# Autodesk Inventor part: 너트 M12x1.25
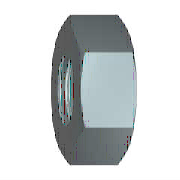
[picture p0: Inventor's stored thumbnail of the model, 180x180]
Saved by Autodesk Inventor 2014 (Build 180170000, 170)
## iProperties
IsCustomPart: 1
Created: 2012-02
Part Number: 너트 M12x1.25
Material: 강철, 연강
Description: 6각 너트
Document SubType Name: Modeling
Standard: KS B 1012
Designer: mduedu
Standards Organization: KS
Language: ko-KR
Size Designation: M12x1.25
Categories: <MemberInstance><Categories><Category DisplayName="조임쇠" InternalName="e4da775c-781d-43d5-af7c-5136215cf5a6" Mnemonic="FSTN"><Category DisplayName="너트" InternalN
Density: 1 g/cm^3
Appearance: 강철
Author: mduedu
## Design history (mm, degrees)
sketch "스케치1"
  geometry: L1 (-10.97, 0)-(-5.485, 9.5); L2 (-5.485, 9.5)-(5.485, 9.5); L3 (5.485, 9.5)-(10.97, 0); L4 (10.97, 0)-(5.485, -9.5); L5 (5.485, -9.5)-(-5.485, -9.5); L6 (-5.485, -9.5)-(-10.97, 0); 2 further points
  constraints: 12 end point, 1 coincident, 1 horizontal, 11 other
  dimensions: "d0" = 21.93931 distance of L3.end L1.start (= 1.1547 x SW)
extrude "본체" new body sketch "스케치1" distance "d1" = 10 (= KOH); taper "d2" = 0 deg
sketch "스케치2"
  geometry: L1 (0, 5.485)-(0, 10.97) reference; L2 (0, 10.97)-(10, 10.97) reference; L3 (10, 5.485)-(10, 10.97) reference; L4 (-2, 0)-(12, 0) reference; L5 (0.849, 10.97)-(0, 9.5); L6 (9.151, 10.97)-(10, 9.5)
  constraints: 4 end point, 4 point on line
  dimensions: "d3" = 30 deg angle of L1 L5 (= ANG1); "d4" = 30 deg angle of L3 L6 (= ANG2); "d5" = 19 diameter of L5.end L4 (= SW0); "d6" = 19 diameter of L6.end L4 (= SW01)
revolve "모따기1" sketch "스케치2" stored, may be unused: angle "d7" = 90 deg
sketch "스케치3"
  geometry: A1 r 9.5 centre (0, 0) between (-4.75, -8.227) and (4.75, -8.227) reference; 1 further point
  constraints: 1 coincident
hole "스레드" sketch "스케치3" at (0, 0) diameter "d25" = 10.647; stored, may be unused: countersink angle "d29" = 82 deg, drill point angle "d31" = 118 deg; dims "d26" = 6, "d27" = 4, "d28" = 2, "d30" = 8
workaxis "Work Axis1"
workplane "Work Plane1"
body "Solid1"
chamfer "모따기2" distance "d8" = 0.67658 (= -0.5 x GD1 + 0.5 x NND); stored, may be unused: angle "d9" = 30 deg, second distance "d40" = 0.67658 (= -0.5 x GD1 + 0.5 x NND)
chamfer "모따기3" distance "d10" = 0.67658 (= -0.5 x GD1 + 0.5 x NND); stored, may be unused: angle "d11" = 30 deg, second distance "d41" = 0.67658 (= -0.5 x GD1 + 0.5 x NND)
other parameters: "ANG1" = 30 deg [user parameter; used in 1 equation term], "ANG2" = 30 deg [user parameter; used in 1 equation term], "NND" = 12 [user parameter; used in 4 equation terms], "KOH" = 10 [user parameter; used in 1 equation term], "SW" = 19 [user parameter; used in 4 equation terms], "SW0" = 19 (= SW) [user parameter; used in 1 equation term], "SW01" = 19 (= SW) [user parameter; used in 1 equation term], "GD1" = 10.64684 (computed from THREADDIA, PTC, TOA) [user parameter; used in 4 equation terms], "d13" = 0, "d14" = 0, "d39" = 0, "d42" = 0, "GUL" = 0.67658 (= 0.541266 x PTC) [user parameter], "TPU" = 8 (computed from PTC) [user parameter], "THREADDIA" = 12 [user parameter; used in 1 equation term], "TOA" = 30 deg [user parameter; used in 1 equation term], "PTC" = 1.25 [user parameter; used in 4 equation terms], "E0" = 21.945 (= 1.155 x SW) [user parameter], "GAL" = 0.67658 (= 0.541266 x PTC) [user parameter]
